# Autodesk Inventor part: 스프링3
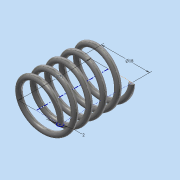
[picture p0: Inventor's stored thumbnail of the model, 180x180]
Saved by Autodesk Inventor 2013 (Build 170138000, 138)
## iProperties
Created: 2016-10
Part Number: 스프링3
Material: 강철, 탄소
Document SubType Name: Modeling
Designer: user
Mass: 6.88075 g
Surface Area: 17.7314 cm^2
Volume: 0.874302 cm^3
Density: 7.87 g/cm^3
Author: user
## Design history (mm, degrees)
sketch "스케치1"
  geometry: L1 (0, 0)-(9, 0); L2 (9, 0)-(9, 27); L3 (9, 27)-(0, 27); L4 (0, 27)-(0, 0); C1 r 1 at (9, 0)
  constraints: 8 end point, 2 parallel, 1 centre point, 1 coincident, 1 horizontal, 1 perpendicular
  dimensions: "d0" = 27 distance of L3.end L1.start (derived); "d1" = 18 diameter of L2 L4; "d2" = 2 diameter of C1
feature "코일1" pitch "d3" = 10; turns "d5" = 5; dims "d4" = 27 (= d0), "d6" = 0, angle "d7" = 90 deg, angle "d8" = 90 deg, "d9" = 0, "d10" = 0
sketch "스케치2"
  geometry: L1 (-8, 0)-(-10, 0) reference; 1 further point
  constraints: 1 horizontal alignment
extrude "돌출1" cut sketch "스케치2" distance "d11" = 10; taper "d12" = 0 deg
node "작업 평면1"
sketch "스케치3"
  geometry: L1 (-1, 0)-(1, 0) reference; 1 further point
  constraints: 1 horizontal alignment
extrude "돌출2" cut sketch "스케치3" distance "d14" = 10; taper "d15" = 0 deg
node "솔리드1"
node "절단 모서리 투영1"
node "절단 모서리 투영2"
other parameters: "d13" = 0
